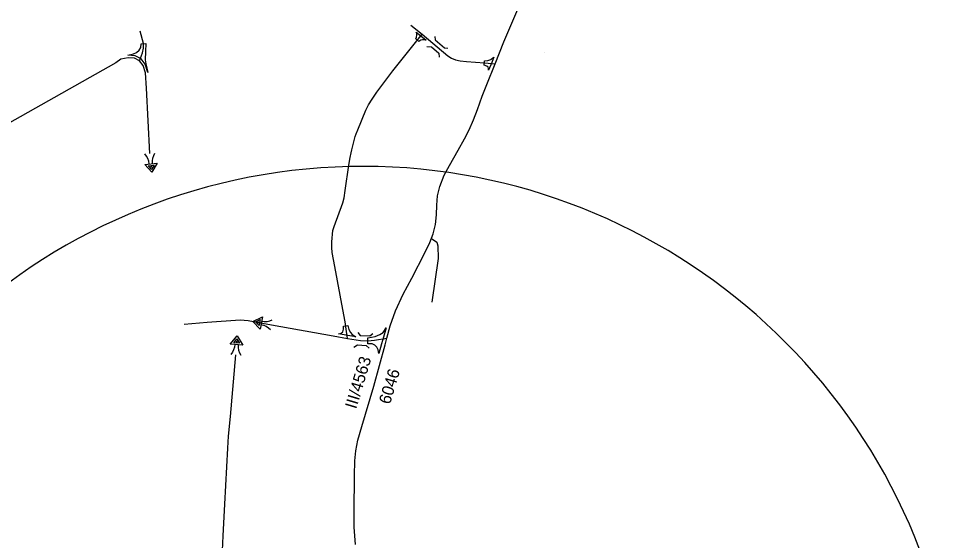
# Model space of a CAD drawing. Extents: x -546703 to -534152, y -1046534 to -1035676.
# Drawn here: x -542893 to -542104, y -1039506 to -1039069 of the extents above; entities that cross this region are included whole.
import ezdxf

# ---------------------------------------------------------------- set-up
doc = ezdxf.new("R2010")
doc.units = 0
for name, color, linetype in [('Vrstva 11', 7, 'Continuous'), ('Vrstva 22', 7, 'Continuous'), ('Vrstva 26', 7, 'Continuous'), ('Vrstva 37', 7, 'Continuous'), ('Vrstva 4', 7, 'Continuous'), ('Vrstva 7', 7, 'Continuous'), ('Vrstva 8', 7, 'Continuous')]:
    doc.layers.add(name, color=color, linetype=linetype)

msp = doc.modelspace()

# ---------------------------------------------------------------- linework, layer by layer
at = {"layer": 'Vrstva 11'}
msp.add_line((-542451.74, -1039097.12), (-542451.74, -1039097.12), dxfattribs=at)
for points in [[(-542791.37, -1039103.97), (-542788.8, -1039097.2), (-542788.12, -1039093.33), (-542788.02, -1039089.55), (-542790.83, -1039079)], [(-542782.67, -1039181.62), (-542785.62, -1039126.82), (-542786.45, -1039114.16), (-542788.42, -1039107.75), (-542791.37, -1039103.97), (-542795.65, -1039101.67), (-542801.07, -1039101.34), (-542806.98, -1039102.66), (-542811.19, -1039105.69), (-543021.99, -1039224.21), (-543121.04, -1039281.55), (-543142.15, -1039293.12), (-543153.54, -1039298.46), (-543159.93, -1039300.3), (-543173.23, -1039303.66), (-543334.11, -1039335.78), (-543466.72, -1039363.98), (-543475.43, -1039365.63), (-543482.21, -1039366.4), (-543489.08, -1039366.31), (-543493.17, -1039366.73), (-543500.21, -1039366.11), (-543511.85, -1039362.9), (-543552.26, -1039343.92)], [(-542718.71, -1039653.17), (-542719.51, -1039644.58), (-542720.38, -1039634.9), (-542721.05, -1039626.38), (-542721.54, -1039619.12), (-542721.92, -1039580.29), (-542722.22, -1039543.97), (-542722.31, -1039531), (-542722.02, -1039523.25), (-542721.73, -1039514.15), (-542721.25, -1039502.04), (-542719.8, -1039475.32), (-542717.38, -1039428.45), (-542716.7, -1039418.38), (-542715.25, -1039401.82), (-542710.78, -1039350.27)]]:
    msp.add_lwpolyline(points, dxfattribs=at)
msp.add_lwpolyline([(-542801.23, -1039099.33), (-542796.35, -1039098.17), (-542793.93, -1039097.01), (-542791.6, -1039095.07), (-542790.44, -1039092.85), (-542790.03, -1039089.79), (-542786.02, -1039089.32), (-542786.48, -1039096.25), (-542786.67, -1039103.01), (-542786.09, -1039106.5), (-542784.47, -1039113.8), (-542786.61, -1039106.81), (-542790.06, -1039102.41), (-542795.09, -1039099.7)], close=True, dxfattribs=at)
at = {"layer": 'Vrstva 22'}
msp.add_lwpolyline([(-542610.4, -1039509.13), (-542611.42, -1039494.6), (-542611.55, -1039481.87), (-542611.22, -1039451.51), (-542610.88, -1039439.1), (-542610.19, -1039430.69), (-542608.47, -1039421.8), (-542605.16, -1039410.22), (-542595.04, -1039376.66), (-542585.6, -1039341.78), (-542584.08, -1039336.2), (-542581.19, -1039326.06), (-542576.78, -1039313.45), (-542570.44, -1039299.39), (-542563.28, -1039286.09), (-542552.4, -1039264.93), (-542548.13, -1039256.31), (-542545.3, -1039248.87), (-542543.3, -1039241.08), (-542542.41, -1039233.09), (-542542.2, -1039224.88), (-542541.65, -1039217.16), (-542539.58, -1039209.24), (-542535.93, -1039199.73), (-542531.52, -1039191.59), (-542524.43, -1039178.84), (-542519.13, -1039169.19), (-542515.2, -1039161.82), (-542511.55, -1039153.27), (-542508.1, -1039144.86), (-542504.18, -1039133.56), (-542500.39, -1039123.77), (-542493.45, -1039106.55), (-542486.08, -1039088.09), (-542472.77, -1039056.78)], dxfattribs=at)
at = {"layer": 'Vrstva 26'}
msp.add_arc((-542604.39, -1039692.44), 500, 284.37443, 180.94243, dxfattribs=at)
at = {"layer": 'Vrstva 37'}
for points in [[(-542783.26, -1039190.33), (-542783.65, -1039188.06), (-542784.39, -1039185.89), (-542785.46, -1039183.86), (-542786.83, -1039182.01)], [(-542780.47, -1039190.06), (-542780.51, -1039187.77), (-542780.19, -1039185.49), (-542779.52, -1039183.3), (-542778.52, -1039181.23)], [(-542689.12, -1039322.13), (-542686.84, -1039322.35), (-542684.54, -1039322.22), (-542682.3, -1039321.73), (-542680.16, -1039320.9)], [(-542689.61, -1039324.89), (-542687.38, -1039325.46), (-542685.28, -1039326.37), (-542683.34, -1039327.6), (-542681.61, -1039329.11)], [(-542711.5, -1039341.58), (-542711.86, -1039343.85), (-542712.56, -1039346.03), (-542713.6, -1039348.08), (-542714.93, -1039349.95)], [(-542708.71, -1039341.79), (-542708.71, -1039344.09), (-542708.36, -1039346.36), (-542707.65, -1039348.54), (-542706.62, -1039350.59)]]:
    msp.add_lwpolyline(points, dxfattribs=at)
for points in [[(-542781.19, -1039197.37), (-542787.1, -1039190.69), (-542776.64, -1039189.7)], [(-542781.42, -1039195), (-542784.23, -1039191.82), (-542779.25, -1039191.35)], [(-542781.57, -1039193.35), (-542782.22, -1039192.62), (-542781.08, -1039192.51)], [(-542696.46, -1039322.26), (-542688.45, -1039318.34), (-542690.28, -1039328.68)], [(-542694.12, -1039322.67), (-542690.31, -1039320.81), (-542691.18, -1039325.73)], [(-542692.48, -1039322.96), (-542691.61, -1039322.53), (-542691.81, -1039323.66)], [(-542709.55, -1039334.5), (-542704.87, -1039342.09), (-542715.34, -1039341.28)], [(-542709.73, -1039336.87), (-542707.51, -1039340.48), (-542712.49, -1039340.1)], [(-542709.86, -1039338.53), (-542709.35, -1039339.36), (-542710.49, -1039339.27)]]:
    msp.add_lwpolyline(points, close=True, dxfattribs=at)
at = {"layer": 'Vrstva 4'}
msp.add_lwpolyline([(-542610.4, -1039509.13), (-542611.42, -1039494.6), (-542611.55, -1039481.87), (-542611.22, -1039451.51), (-542610.88, -1039439.1), (-542610.19, -1039430.69), (-542608.47, -1039421.8), (-542605.16, -1039410.22), (-542595.04, -1039376.66), (-542585.6, -1039341.78), (-542584.08, -1039336.2), (-542581.19, -1039326.06), (-542576.78, -1039313.45), (-542570.44, -1039299.39), (-542563.28, -1039286.09), (-542552.4, -1039264.93), (-542548.13, -1039256.31), (-542545.3, -1039248.87), (-542543.3, -1039241.08), (-542542.41, -1039233.09), (-542542.2, -1039224.88), (-542541.65, -1039217.16), (-542539.58, -1039209.24), (-542535.93, -1039199.73), (-542531.52, -1039191.59), (-542524.43, -1039178.84), (-542519.13, -1039169.19), (-542515.2, -1039161.82), (-542511.55, -1039153.27), (-542508.1, -1039144.86), (-542504.18, -1039133.56), (-542500.39, -1039123.77), (-542493.45, -1039106.55), (-542486.08, -1039088.09), (-542472.77, -1039056.78)], dxfattribs=at)
at = {"layer": 'Vrstva 7'}
for points in [[(-542564.03, -1039074.1), (-542554.56, -1039081.58), (-542533.1, -1039099.67), (-542529.89, -1039101.61), (-542526.58, -1039103.05), (-542522.7, -1039104.1), (-542517.35, -1039104.57), (-542502.35, -1039105.73), (-542493.45, -1039106.55)], [(-542617.14, -1039336.54), (-542618.21, -1039328.85), (-542619.1, -1039322.76), (-542621.03, -1039312.41), (-542627.78, -1039276.28), (-542629.88, -1039264.6), (-542630.21, -1039260.34), (-542630.32, -1039255.58), (-542629.38, -1039246.01), (-542628.22, -1039242.75), (-542620.87, -1039222.88), (-542619.98, -1039218.84), (-542619.1, -1039212.65), (-542616.06, -1039191.45), (-542614.95, -1039185.09), (-542614.07, -1039181.16), (-542613.57, -1039178.61), (-542610.64, -1039167.33), (-542609.81, -1039165.11), (-542608.42, -1039161.68), (-542601.62, -1039145.3), (-542599.47, -1039140.88), (-542596.37, -1039135.95), (-542592.5, -1039130.25), (-542579.06, -1039112.38), (-542554.56, -1039081.58)], [(-542546.76, -1039252.79), (-542542.32, -1039256.01), (-542541.31, -1039259.04), (-542541.11, -1039269.53), (-542546.36, -1039306.03)], [(-542753.98, -1039324.48), (-542734.62, -1039322.97), (-542707.19, -1039320.85), (-542700.34, -1039321.46), (-542680.89, -1039325.01), (-542629.07, -1039334.45), (-542617.14, -1039336.54), (-542606.1, -1039338.25), (-542600.02, -1039338.47), (-542594.38, -1039338.09), (-542584.08, -1039336.2)]]:
    msp.add_lwpolyline(points, dxfattribs=at)
for points in [[(-542559.95, -1039085.55), (-542559.26, -1039084.01), (-542558.98, -1039082.47), (-542559.04, -1039081.03), (-542559.53, -1039079.88), (-542555.66, -1039082.94), (-542551.18, -1039086.72), (-542552.79, -1039086.34), (-542554.17, -1039086.39), (-542555.61, -1039086.67), (-542557.21, -1039087.72)], [(-542502.21, -1039103.99), (-542499.42, -1039103.71), (-542496.99, -1039102.72), (-542495.27, -1039101.56), (-542494.45, -1039100.95), (-542496.24, -1039105.43), (-542498.81, -1039111.83), (-542498.98, -1039110.3), (-542499.31, -1039109.3), (-542500.25, -1039108.47), (-542502.5, -1039107.48)], [(-542616.74, -1039334.07), (-542624.54, -1039332.71), (-542622.36, -1039332.17), (-542620.98, -1039330.89), (-542620.43, -1039328.85), (-542620.35, -1039326.31), (-542616.92, -1039325.6), (-542615.89, -1039329.12), (-542614.67, -1039331.5), (-542613.29, -1039333.33), (-542610.04, -1039335.11)], [(-542600.06, -1039335.97), (-542593.88, -1039334.99), (-542589.9, -1039333.27), (-542587.24, -1039331.56), (-542584.74, -1039327.58), (-542586.97, -1039335.39), (-542588.49, -1039341), (-542590.72, -1039349.23), (-542591.34, -1039346.11), (-542592.44, -1039343.95), (-542594.16, -1039342.13), (-542596.31, -1039341.19), (-542599.98, -1039340.98)]]:
    msp.add_lwpolyline(points, close=True, dxfattribs=at)
at = {"layer": 'Vrstva 8'}
for points in [[(-542543.95, -1039083.61), (-542543.64, -1039086.48), (-542535.85, -1039093.06), (-542532.98, -1039093.38)], [(-542550.7, -1039091.94), (-542546.8, -1039092.26), (-542540.57, -1039097.68), (-542540.17, -1039100.79)], [(-542608.52, -1039331.55), (-542606.61, -1039334.02), (-542598.4, -1039334.5), (-542595.93, -1039332.34)], [(-542611.75, -1039343.81), (-542608.64, -1039341.9), (-542601.31, -1039342.38), (-542598.99, -1039344.77)]]:
    msp.add_lwpolyline(points, dxfattribs=at)

# ---------------------------------------------------------------- texts
at = {"layer": 'Vrstva 22'}
msp.add_text('6046', height=10, rotation=73.35706, dxfattribs=at).set_placement((-542581.51, -1039392.32))
at = {"layer": 'Vrstva 4'}
msp.add_text('III/4563', height=10, rotation=73.35706, dxfattribs=at).set_placement((-542609.8, -1039396.17))

doc.saveas('drawing.dxf')
